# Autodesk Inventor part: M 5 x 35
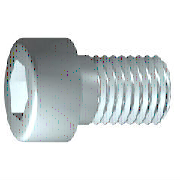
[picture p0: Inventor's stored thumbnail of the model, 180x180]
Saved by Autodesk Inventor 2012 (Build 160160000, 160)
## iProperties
IsCustomPart: 0
Company: 한국ATC센터
Created: 2014-12
Part Number: M 5 x 35
Material: 강, 연강
Description: 6각머리 태핑 나사
Document SubType Name: Modeling
Standard: KS B 1003
Designer: KYOUNG IL JANG
Standards Organization: KS
Language: ko-KR
Size Designation: M 5 x 35
Categories: <MemberInstance><Categories><Category DisplayName="조임쇠" InternalName="e4da775c-781d-43d5-af7c-5136215cf5a6" Mnemonic="FSTN"><Category DisplayName="볼트" InternalN
Density: 7.86 g/cm^3
Mass: 7.27786 g
Surface Area: 8.23857 cm^2
Volume: 0.925936 cm^3
Author: KYOUNG IL JANG
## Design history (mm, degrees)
workplane "Work Plane1"
fillet "Fillet2" dims "d30" = 0.1 (= R)
revolve "본체" stored, may be unused: angle "d10" = 90 deg
sketch "스케치2"
  geometry: L1 (0, -5.95)-(0, 5.95) reference; L2 (-5.95, 0)-(5.95, 0) reference; L3 (2.309, 0)-(1.155, -2); L4 (1.155, -2)-(-1.155, -2); L5 (-1.155, -2)-(-2.309, 0); L6 (-2.309, 0)-(-1.155, 2); L7 (-1.155, 2)-(1.155, 2); L8 (1.155, 2)-(2.309, 0); 2 further points
  constraints: 12 end point, 1 coincident, 1 horizontal alignment, 1 point on line, 12 other
extrude "슬롯" join sketch "스케치2" stored distance "d11" = 10; taper "d12" = 0 deg
body "Solid1"
fillet "모깎기1" dims "d17" = 0.5 (= RR)
feature "스레드" dims "d13" = 22 (= GEL), "d14" = 0
chamfer "모따기1" distance "d15" = 0.49076 (= -0.5 x SPD + 0.5 x GD); stored, may be unused: second distance "d16" = 0.49076 (= GUL), angle "d27" = 45 deg
sketch "스케치1"
  geometry: L1 (-1.167, 0)-(35, 0); L2 (35, 0)-(35, 2.5); L3 (35, 2.5)-(13, 2.5); L4 (13, 2.5)-(12.509, 2.5); L5 (12.509, 2.5)-(0, 2.5); L6 (0, 2.5)-(0, 4.25); L7 (0, 4.25)-(-5, 4.25); L8 (-5, 4.25)-(-5, 2.309); L9 (-5, 2.309)-(-2.5, 2.309); L10 (-2.5, 2.309)-(-1.167, 0); L11 (-13, 0)-(43, 0) reference; L12 (0, -0.85)-(0, 5.1) reference; L13 (13, 2.5)-(0, 2.5)
  constraints: 22 end point, 6 parallel, 2 collinear, 2 perpendicular, 1 horizontal, 1 point on line
  dimensions: "d1" = 22 distance from line of L3.end L2 (= GEL); "d2" = 0.49086 distance of L4.end L3.end (computed from GAL); "d3" = 5 distance between parallel lines of L8 L6 (= KOH); "d4" = 2.5 distance of L8.end L9.end (= INTI); "d5" = 60 deg angle of L10 L1; "d6" = 5 diameter of L3 L1 (= GD); "d7" = 5 diameter of L5 L1 (= BDM); "d8" = 4.6188 diameter of L9 L1 (= 1.1547 x SW); "d9" = 8.5 diameter of L7 L1 (= KOD); "d26" = 35 distance between parallel lines of L12 L2 (= NLG)
other parameters: "GD" = 5 (= NND) [user parameter; used in 2 equation terms], "NLG" = 35 [user parameter; used in 1 equation term], "GEL" = 22 [user parameter; used in 2 equation terms], "KOD" = 8.5 [user parameter; used in 1 equation term], "KOH" = 5 [user parameter; used in 1 equation term], "INTI" = 2.5 [user parameter; used in 1 equation term], "GAL" = 0.49076 (= 0.61345 x PTC) [user parameter; used in 1 equation term], "GUL" = 0.49076 (= 0.61345 x PTC) [user parameter; used in 1 equation term], "BDM" = 5 (= NND) [user parameter; used in 1 equation term], "SW" = 4 [user parameter; used in 2 equation terms], "RR" = 0.5 [user parameter; used in 1 equation term], "SPD" = 4.01848 (= NND - 1.2269 x PTC) [user parameter; used in 1 equation term], "d19" = 0, "d28" = 0, "d29" = 0, "R" = 0.1 [user parameter; used in 1 equation term], "PHH" = 0.2 [user parameter], "GD1" = 4.01848 (= THREADDIA - 1.2269 x PTC) [user parameter], "THREADDIA" = 5 [user parameter; used in 1 equation term], "FAWI" = 45 deg [user parameter], "TPU" = 12.5 (computed from PTC) [user parameter], "PTC" = 0.8 [user parameter; used in 5 equation terms], "NND" = 5 [user parameter; used in 3 equation terms], "TOA" = 30 deg [user parameter], "E0" = 4.62 (= 1.155 x SW) [user parameter]
